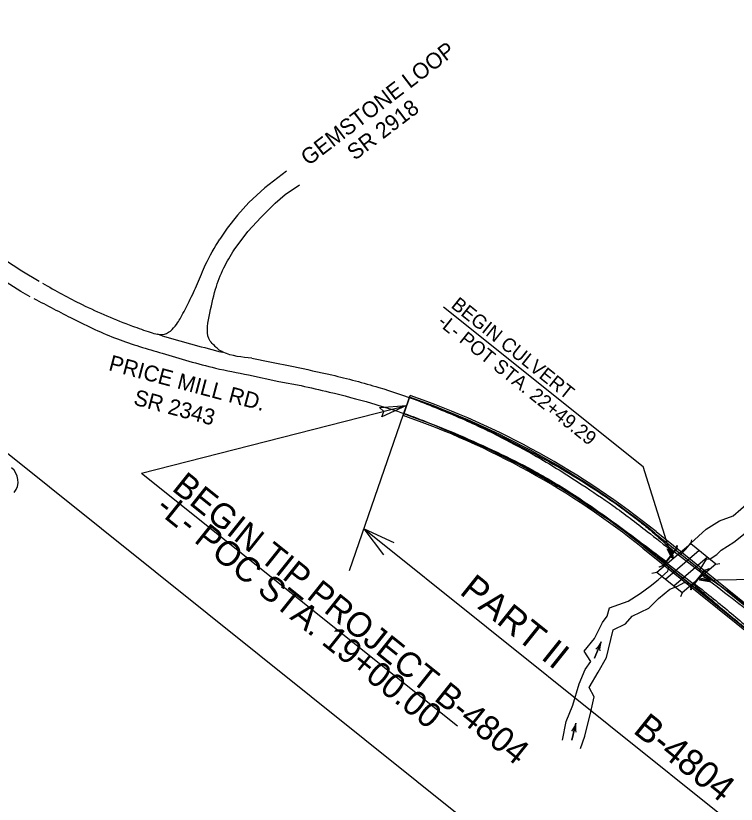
# Model space of a CAD drawing. Extents: x 1730256 to 1738218, y 910410 to 917906.
# Drawn here: x 1734090 to 1734907, y 915111 to 916005 of the extents above; entities that cross this region are included whole.
import ezdxf

# ---------------------------------------------------------------- set-up
doc = ezdxf.new("R2010")
doc.units = 0
for name, color, linetype in [('Default', 7, 'Continuous'), ('Old_Level_23', 7, 'Continuous'), ('Old_Level_3', 7, 'Continuous'), ('Old_Level_5', 7, 'Continuous'), ('Prop DSN Text', 7, 'Continuous'), ('Prop EOT', 7, 'Continuous'), ('Prop Paved Shoulder', 7, 'Continuous'), ('Prop Roadway Bridge', 7, 'Continuous'), ('Prop Roadway Culvert', 7, 'Continuous'), ('Prop Shade Light', 7, 'Continuous'), ('Sheet Title CELL', 7, 'Continuous')]:
    doc.layers.add(name, color=color, linetype=linetype)

# ---------------------------------------------------------------- blocks, each defined once
blk = doc.blocks.new('EXIST HYDRO RIVER FLOW ARROW')
at = {"layer": 'Default'}
blk.add_line((0, 0), (0, 0), dxfattribs=at)
blk.add_lwpolyline([(0, 0.04575), (0.03775, 0.03), (0.07725, 0.01725), (0.118, 0.00775), (0.159, 0.0015), (0.2, 0), (-0.2, 0), (0.2, 0), (0.159, -0.0015), (0.118, -0.00775), (0.07725, -0.01725), (0.03775, -0.03), (0, -0.04575)], dxfattribs=at)

msp = doc.modelspace()

# ---------------------------------------------------------------- linework, layer by layer
at = {"layer": 'Old_Level_23'}
for p, q in [((1734468.28, 915376.37), (1734532.86, 915563.34)), ((1734232.34, 915486.84), (1734590.49, 915200.21)), ((1734484.6, 915423.63), (1734949.55, 915051.53))]:
    msp.add_line(p, q, dxfattribs=at)
at = {"layer": 'Old_Level_3'}
for p, q in [((1734357.47, 915616.92), (1734377.83, 915612.75)), ((1734377.83, 915612.75), (1734404.53, 915607.46)), ((1734353.63, 915598.16), (1734388.2, 915590.72)), ((1734388.2, 915590.72), (1734413.17, 915585.91))]:
    msp.add_line(p, q, dxfattribs=at)
for points in [[(1734116.28, 915703.97), (1734096.48, 915715.84), (1734076.91, 915728.52), (1734054.17, 915744.24), (1734034.88, 915758.56), (1734015.45, 915774.5), (1733997.85, 915789.76), (1733980.47, 915806.17), (1733968.31, 915818.56), (1733958.67, 915828.45)], [(1734396.81, 915829.03), (1734371.98, 915810.24), (1734354.06, 915793.68), (1734341.03, 915779.15), (1734329.38, 915764.28), (1734321.04, 915751.8)], [(1734105.96, 915686.63), (1734095.32, 915692.77), (1734070.1, 915708.44), (1734042.7, 915728.12), (1734017.85, 915747.11), (1733993.14, 915767.73), (1733971.08, 915787.87), (1733956.08, 915802.5), (1733943.66, 915815.24)], [(1734337.51, 915739.92), (1734353, 915760.53), (1734367.85, 915776.95), (1734383.95, 915792.64), (1734395.21, 915802.43), (1734411.29, 915813.39)]]:
    msp.add_lwpolyline(points, dxfattribs=at)
for points in [[(1734119.9, 915702.05), (1734165.06, 915677.81), (1734221.99, 915653.47), (1734242.31, 915646.37), (1734250.64, 915644.1), (1734258.48, 915644.27), (1734266.94, 915649.5), (1734273.29, 915657.25), (1734276.86, 915663.12), (1734286.37, 915681.33), (1734295.68, 915701.62), (1734304.88, 915723.1), (1734321.04, 915751.8)], [(1734357.47, 915616.92), (1734324.71, 915623.9), (1734319.09, 915627.25), (1734314.94, 915631.25), (1734310.25, 915636.38), (1734309.03, 915664.08), (1734316.27, 915695.26), (1734325.69, 915719.41), (1734337.51, 915739.92)], [(1734110.36, 915684.67), (1734154.76, 915661.6), (1734204.92, 915638.83), (1734255.88, 915622.54), (1734316.16, 915605.77), (1734353.63, 915598.16)], [(1734404.53, 915607.46), (1734448.1, 915598.02), (1734501.36, 915583.86), (1734545.73, 915568.91), (1734602.15, 915546.23), (1734644.67, 915526.02), (1734702.53, 915494.94), (1734740.42, 915472.04), (1734778.1, 915446.26), (1734796.07, 915432.73), (1734808.87, 915422.33), (1734820.03, 915412.62), (1734836.33, 915397.67)], [(1734413.17, 915585.91), (1734445.14, 915578.64), (1734492.96, 915566.03), (1734551.95, 915546.2), (1734598.84, 915525.94), (1734659.7, 915496.79), (1734686.52, 915481.69), (1734709.59, 915468.75), (1734743.42, 915446.6), (1734767.44, 915430.19), (1734789.72, 915413.44), (1734818.54, 915391.98), (1734826.76, 915385.43)], [(1734545.73, 915568.91), (1734598.79, 915547.08), (1734645.22, 915524.62), (1734685.17, 915502.8), (1734731.94, 915473.54), (1734766.74, 915449.9), (1734805.67, 915420.68), (1734834.64, 915397.68)], [(1734545.73, 915568.91), (1734598.79, 915547.08), (1734645.22, 915524.62), (1734685.17, 915502.8), (1734731.94, 915473.54), (1734766.74, 915449.9), (1734805.67, 915420.68), (1734834.64, 915397.68)], [(1734551.95, 915546.2), (1734591.67, 915530.17), (1734635.65, 915510.29), (1734675.17, 915490.38), (1734723.26, 915461.69), (1734760.6, 915436.08), (1734796.66, 915409.53), (1734827.4, 915386.51)], [(1734551.95, 915546.2), (1734591.67, 915530.17), (1734635.65, 915510.29), (1734675.17, 915490.38), (1734723.26, 915461.69), (1734760.6, 915436.08), (1734796.66, 915409.53), (1734827.4, 915386.51)], [(1734867.86, 915373.07), (1734891.7, 915356.76), (1734930.33, 915326.02), (1734970.32, 915291.99), (1735005.27, 915261.32), (1735024.06, 915243.43), (1735033.15, 915234.18), (1735042.14, 915224.81), (1735056.21, 915209.41), (1735069.65, 915193.46), (1735086.65, 915171.45), (1735102.74, 915148.77), (1735125.96, 915112.12), (1735140.95, 915084.89), (1735155.38, 915057.39), (1735158.12, 915051.66), (1735159.45, 915048.78), (1735160.89, 915045.93), (1735165.87, 915039.38), (1735172.8, 915033), (1735180.64, 915028.28), (1735182.57, 915027.8), (1735184.51, 915027.58), (1735188.38, 915027.7), (1735201.89, 915029.6), (1735214.29, 915032.53), (1735224.55, 915035.86)], [(1734867.91, 915371.3), (1734901.92, 915344.86), (1734933.09, 915320.66), (1734950.45, 915306.67), (1734981.89, 915280.2), (1735021.66, 915243.96), (1735053.56, 915211.01), (1735069.65, 915193.46)], [(1734867.91, 915371.3), (1734901.92, 915344.86), (1734933.09, 915320.66), (1734950.45, 915306.67), (1734981.89, 915280.2), (1735021.66, 915243.96), (1735053.56, 915211.01), (1735069.65, 915193.46)], [(1734858.22, 915360.67), (1734895.64, 915328.62), (1734934.22, 915297.2), (1734972.7, 915264.77), (1735005.94, 915234.2), (1735039.93, 915198.24), (1735072.41, 915158), (1735096.75, 915123.08), (1735121.96, 915080.08), (1735142.34, 915040.74), (1735163.87, 914992.3), (1735179.09, 914950.63), (1735193.56, 914895.57), (1735202.84, 914849.68), (1735206.11, 914828.68)], [(1734860.08, 915360.81), (1734901.23, 915327.52), (1734939.09, 915295.34), (1734975.42, 915263.7), (1735005.94, 915234.2)], [(1734860.08, 915360.81), (1734901.23, 915327.52), (1734939.09, 915295.34), (1734975.42, 915263.7), (1735005.94, 915234.2)]]:
    msp.add_spline(points, degree=3, dxfattribs=at)
at = {"layer": 'Old_Level_5'}
for points in [[(1734842.2, 915393.26), (1734849.26, 915399.96), (1734854.95, 915407.39), (1734872.33, 915423.08), (1734887.54, 915432.8), (1734903.06, 915438.24), (1734920.36, 915453.61), (1734941.62, 915469.24), (1734967.32, 915489.78), (1734996.6, 915510.63), (1734997.24, 915527.41), (1735007.05, 915536.59), (1735033.32, 915541.68)], [(1734864.64, 915375.65), (1734872.89, 915389.34), (1734877.09, 915389.68), (1734884.72, 915394.32), (1734889.7, 915399.34), (1734903.75, 915408.63), (1734916.66, 915418.71), (1734924.09, 915424.15), (1734933.66, 915430.75), (1734941.81, 915441.88), (1734946.57, 915450.27), (1734954.38, 915452.81), (1734974.19, 915468.68), (1734987.64, 915477.42), (1734997.51, 915481.05), (1735010.34, 915492.29), (1735024.21, 915501.95), (1735029.03, 915508.6), (1735050.33, 915521.75)], [(1734709.56, 915183.83), (1734713.62, 915205.2), (1734721.31, 915223.6), (1734728.64, 915247.96), (1734735.42, 915264.09), (1734741.78, 915273.08), (1734734.09, 915284.73), (1734745.73, 915299.26), (1734754.84, 915317.54), (1734760.39, 915324.45), (1734763.07, 915334.09), (1734784.2, 915341.63), (1734797.75, 915350.25), (1734808.84, 915358.61), (1734818.1, 915365.79), (1734829.01, 915375.45), (1734830.23, 915380.19)], [(1734730.09, 915174.43), (1734734.77, 915188.73), (1734741.89, 915216.24), (1734745.58, 915233.04), (1734739.99, 915243.88), (1734749.93, 915261.08), (1734759.65, 915277.62), (1734761.69, 915287.24), (1734767.15, 915309.18), (1734781.15, 915315.85), (1734788.61, 915324.62), (1734807.38, 915333.63), (1734818.38, 915344.44), (1734831.46, 915355.28), (1734839.89, 915358.64), (1734847.64, 915362.75), (1734854.05, 915361.61)]]:
    msp.add_lwpolyline(points, dxfattribs=at)
at = {"layer": 'Prop DSN Text'}
for p, q in [((1734574.81, 915675.41), (1734801.22, 915494.22)), ((1734232.34, 915486.84), (1734532.86, 915563.34)), ((1734833.43, 915390.65), (1734801.22, 915494.22)), ((1734839.24, 915404.5), (1734839.49, 915404.47)), ((1734826.57, 915385.58), (1734836.13, 915397.82)), ((1734836.33, 915397.67), (1734826.76, 915385.43)), ((1734867.86, 915373.07), (1734836.33, 915397.67)), ((1734867.86, 915373.07), (1734836.33, 915397.67)), ((1734819.5, 915380.24), (1734819.41, 915380.48)), ((1734858.22, 915360.67), (1734867.86, 915373.07)), ((1734868.05, 915372.92), (1734858.41, 915360.51)), ((1734875.9, 915378.56), (1734875.99, 915378.32)), ((1734865, 915365.22), (1735020.92, 915368.23)), ((1734855.42, 915354.41), (1734855.17, 915354.44))]:
    msp.add_line(p, q, dxfattribs=at)
for points in [[(1734255.73, 915642.51), (1734250.64, 915644.1)], [(1734320.11, 915624.74), (1734324.71, 915623.9)], [(1734507.07, 915394.1), (1734484.6, 915423.63), (1734518.32, 915408.15)], [(1734836.13, 915397.82), (1734839.17, 915401.91), (1734838.95, 915402.1), (1734839.24, 915404.5)], [(1734839.49, 915404.47), (1734839.21, 915402.2), (1734839.51, 915401.94), (1734836.33, 915397.67)], [(1734867.86, 915373.07), (1734858.22, 915360.67), (1734826.76, 915385.43), (1734836.33, 915397.67)], [(1734867.86, 915373.07), (1734858.22, 915360.67), (1734826.76, 915385.43), (1734836.33, 915397.67)], [(1734819.41, 915380.48), (1734822.7, 915381.77), (1734823.79, 915382.1), (1734826.57, 915385.58)], [(1734826.76, 915385.43), (1734823.94, 915381.88), (1734822.79, 915381.53), (1734819.5, 915380.24)], [(1734867.86, 915373.07), (1734870.87, 915377.07), (1734871.26, 915376.79), (1734875.9, 915378.56)], [(1734875.99, 915378.32), (1734871.23, 915376.5), (1734870.93, 915376.72), (1734868.05, 915372.92)], [(1734855.17, 915354.44), (1734855.38, 915356.23), (1734854.87, 915356.59), (1734858.22, 915360.67)], [(1734858.41, 915360.51), (1734855.23, 915356.64), (1734855.65, 915356.35), (1734855.42, 915354.41)]]:
    msp.add_lwpolyline(points, dxfattribs=at)
for points in [[(1734502.07, 915561), (1734532.86, 915563.34), (1734504.7, 915550.66), (1734507.01, 915556.75)], [(1734831.95, 915402.14), (1734833.43, 915390.65), (1734828.13, 915400.95), (1734830.46, 915400.2)], [(1734833.47, 915400.91), (1734834.95, 915389.43), (1734829.65, 915399.72), (1734831.98, 915398.98)], [(1734874.92, 915364.66), (1734863.48, 915366.44), (1734874.84, 915368.66), (1734873.48, 915366.64)], [(1734876.44, 915363.44), (1734865, 915365.22), (1734876.36, 915367.44), (1734875, 915365.41)]]:
    msp.add_lwpolyline(points, close=True, dxfattribs=at)
msp.add_ellipse((1734704.42, 917202.53), major_axis=(1570.85, -630.82), ratio=0.95853, start_param=4.810004, end_param=4.849482, dxfattribs=at)
at = {"layer": 'Prop EOT'}
for p, q in [((1734529.6, 915553.88), (1734536.13, 915572.79)), ((1734814.41, 915418.82), (1734962.69, 915299.36)), ((1734801.86, 915403.24), (1734950.14, 915283.79))]:
    msp.add_line(p, q, dxfattribs=at)
for radius in [925, 905]:
    msp.add_arc((1734234.11, 914698.48), radius, 51.14521, 70.94317, dxfattribs=at)
at = {"layer": 'Prop Paved Shoulder'}
for p, q in [((1734536.13, 915572.79), (1734536.78, 915574.68)), ((1734528.94, 915551.99), (1734529.6, 915553.88)), ((1734815.66, 915420.37), (1734963.94, 915300.92)), ((1734800.6, 915401.68), (1734948.89, 915282.23))]:
    msp.add_line(p, q, dxfattribs=at)
for radius in [927, 903]:
    msp.add_arc((1734234.11, 914698.48), radius, 51.14521, 70.94317, dxfattribs=at)
at = {"layer": 'Prop Roadway Bridge'}
for p, q in [((1734855.13, 915406.63), (1734856.29, 915411.25)), ((1734855.13, 915406.63), (1734816.72, 915373.89)), ((1734864.64, 915398.97), (1734826.23, 915366.22)), ((1734874.15, 915391.31), (1734835.74, 915358.56)), ((1734883.66, 915383.65), (1734845.25, 915350.9)), ((1734883.66, 915383.65), (1734888.09, 915384.41)), ((1734816.72, 915373.89), (1734811.1, 915372.89)), ((1734845.25, 915350.9), (1734843.55, 915346.42))]:
    msp.add_line(p, q, dxfattribs=at)
at = {"layer": 'Prop Roadway Culvert'}
for p, q in [((1734883.66, 915383.65), (1734855.13, 915406.63)), ((1734845.25, 915350.9), (1734816.72, 915373.89))]:
    msp.add_line(p, q, dxfattribs=at)
at = {"layer": 'Prop Shade Light'}
for p, q in [((1734536.13, 915572.79), (1734529.6, 915553.88)), ((1734814.41, 915418.82), (1734962.69, 915299.36)), ((1734950.14, 915283.79), (1734801.86, 915403.24))]:
    msp.add_line(p, q, dxfattribs=at)
for radius in [925, 905]:
    msp.add_arc((1734234.11, 914698.48), radius, 51.14521, 70.94317, dxfattribs=at)
at = {"layer": 'Sheet Title CELL'}
msp.add_line((1733396.21, 916056.64), (1735613.55, 914282.1), dxfattribs=at)
msp.add_arc((1734072.4, 915477.17), 20, 321.32968, 51.32968, dxfattribs=at)

# ---------------------------------------------------------------- block references
at = {"layer": 'Prop DSN Text'}
for p, xscale, yscale, rotation in [((1734749.67, 915286.18), 50, 50, 68.33644777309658), ((1734722.51, 915193.68), 49.99999999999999, 50.00000000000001, 77.07402072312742)]:
    msp.add_blockref('EXIST HYDRO RIVER FLOW ARROW', p, dxfattribs=dict(at, xscale=xscale, yscale=yscale, rotation=rotation))

# ---------------------------------------------------------------- texts
at = {"layer": 'Old_Level_23'}
for s, height, p in [('BEGIN TIP PROJECT B-4804', 28, (1734265.62, 915467.89)), ('-L- POC STA. 19+00.00', 28, (1734246.88, 915444.47)), ('PART II          B-4804', 30, (1734591.82, 915350.62))]:
    msp.add_text(s, height=height, rotation=321.32968, dxfattribs=at).set_placement(p)
at = {"layer": 'Prop DSN Text'}
for s, height, rotation, p in [('GEMSTONE LOOP', 18, 37.31588, (1734421.6, 915834.5)), ('SR 2918', 18, 37.31588, (1734474.13, 915840.54)), ('BEGIN CULVERT', 15.75, 321.32968, (1734582.29, 915675.19)), ('-L- POT STA. 22+49.29', 15.75, 321.32968, (1734566.83, 915655.86)), ('PRICE MILL RD.', 18, 345.15725, (1734194.05, 915603.58)), ('SR 2343', 18, 345.15725, (1734222.26, 915564.59))]:
    msp.add_text(s, height=height, rotation=rotation, dxfattribs=at).set_placement(p)

doc.saveas('drawing.dxf')
